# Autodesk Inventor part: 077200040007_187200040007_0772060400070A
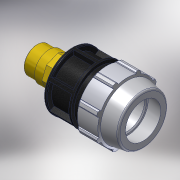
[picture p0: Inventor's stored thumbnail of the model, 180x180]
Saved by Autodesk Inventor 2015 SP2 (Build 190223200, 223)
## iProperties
Created: 2017-02
Part Number: 077200040007_187200040007_0772060400070A
Material: PVC-Piping
Description: PLASSON MALE ADAPTOR WITH INTEGRAL BRASS THREAD 40-3/4"
Document SubType Name: Modeling
Designer: KIM
Mass: 92.6774 g
Surface Area: 199.44 cm^2
Volume: 66.1981 cm^3
Density: 1.4 g/cm^3
Appearance: PTFE
Author: KIM
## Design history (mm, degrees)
derived "07720.ipt"
feature "Solid1::07720.ipt"
tag "TaggingFeature1"
body "Solid1"
other parameters: "d4" = 21.28571, "d5" = 21.28571, "d7" = 82, "d8" = 61.5, "d9" = 21.28571, "d11" = 4.25714, "d12" = 65.6, "d13" = 120 deg, "d15" = 10 deg, "d16" = 73.8, "d18" = 2, "d19" = 35 deg, "d20" = 17.5 deg, "d21" = 76.26, "d23" = 0, "d25" = 360 deg, "d27" = 1.64, "d34" = 4.1, "d36" = 0, "d42" = 29.8, "d43" = 2.46, "d46" = 1.2, "d49" = 91, "d51" = 149, "d53" = 0.8, "d55" = 360 deg, "d59" = 29.8, "d60" = 26.441, "d61" = 29.0851, "d62" = 18, "d63" = 49.66667, "d64" = 18.5087, "d65" = 149, "d66" = 18.08406, "d67" = 0, "d68" = 0.8, "d71" = 30 deg, "d72" = 23.7969, "E_" = 82, "H_" = 149, "l_" = 91, "l_2" = 18, "R_" = 26.441, "d73" = 30.14009
